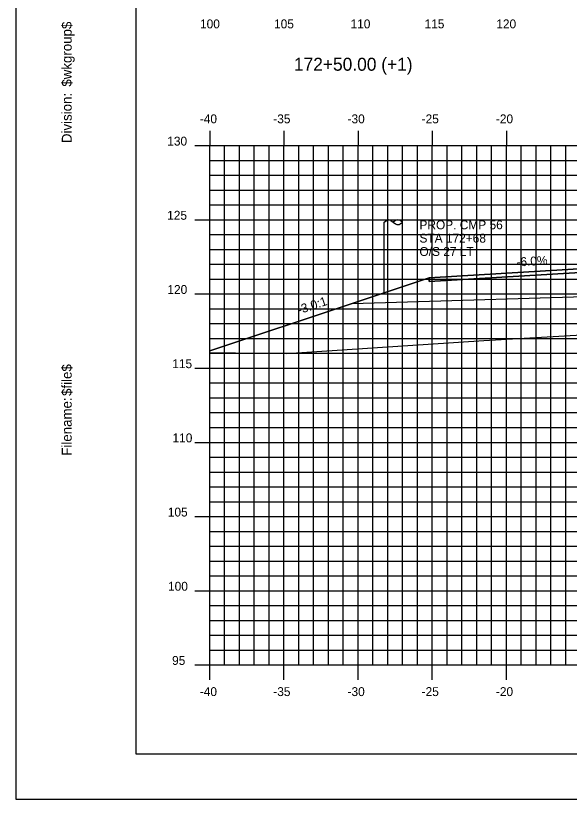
# Model space of a CAD drawing. Extents: x 850598 to 870284, y 366541 to 366651.
# Drawn here: x 856585.2 to 856622.6, y 366541.2 to 366594 of the extents above; entities that cross this region are included whole.
import ezdxf

# ---------------------------------------------------------------- set-up
doc = ezdxf.new("R2010")
doc.units = 0
for name, color, linetype in [('ANNOTATION', 7, 'Continuous'), ('BORDER', 7, 'Continuous'), ('D_Roadway_Centerline', 7, 'Continuous'), ('D_Roadway_Edge_Shoulder', 7, 'Continuous'), ('D_Roadway_SlopeLines', 7, 'Continuous'), ('D_Roadway_SubGrade', 7, 'Continuous'), ('D_Utilities_Pole_Joint', 7, 'Continuous'), ('H_V ANNOTATION', 7, 'Continuous'), ('MAJOR', 7, 'Continuous'), ('MINOR', 7, 'Continuous'), ('PLOT BOUNDARY', 7, 'Continuous'), ('S_Roadway_Centerline', 7, 'Continuous'), ('S_Utilities_Pole_Joint', 7, 'Continuous')]:
    doc.layers.add(name, color=color, linetype=linetype)

msp = doc.modelspace()

# ---------------------------------------------------------------- linework, layer by layer
at = {"layer": 'BORDER'}
for p, q in [((856593.324, 366649.225), (856593.324, 366544.225)), ((856593.324, 366544.225), (856753.324, 366544.225))]:
    msp.add_line(p, q, dxfattribs=at)
at = {"layer": 'D_Roadway_Centerline'}
msp.add_lwpolyline([(856598.324, 366571.386), (856607.935, 366574.589), (856613.124, 366576.319), (856627.324, 366577.171), (856638.324, 366577.501), (856649.324, 366577.171), (856653.324, 366576.931), (856655.324, 366576.811), (856661.324, 366574.811), (856719.255, 366563.221), (856738.324, 366559.406)], dxfattribs=at)
at = {"layer": 'D_Roadway_Edge_Shoulder'}
msp.add_lwpolyline([(856627.324, 366577.171), (856613.124, 366576.319), (856613.124, 366576.069), (856626.324, 366576.861), (856627.324, 366576.921)], close=True, dxfattribs=at)
at = {"layer": 'D_Roadway_SlopeLines'}
msp.add_lwpolyline([(856607.935, 366574.589), (856598.324, 366571.386)], dxfattribs=at)
at = {"layer": 'D_Roadway_SubGrade'}
msp.add_lwpolyline([(856627.324, 366576.671), (856626.324, 366576.611), (856626.324, 366576.861), (856613.124, 366576.069), (856613.124, 366576.319), (856607.935, 366574.589), (856627.324, 366575.171)], close=True, dxfattribs=at)
msp.add_lwpolyline([(856613.124, 366576.319), (856607.935, 366574.589), (856613.124, 366576.319)], dxfattribs=at)
at = {"layer": 'D_Utilities_Pole_Joint'}
for p, q in [((856610.074, 366580.061), (856610.23, 366580.171)), ((856610.074, 366575.303), (856610.074, 366580.061)), ((856610.542, 366580.171), (856610.698, 366580.061)), ((856610.854, 366580.171), (856610.698, 366580.061)), ((856610.698, 366580.061), (856610.854, 366579.95)), ((856611.324, 366580.061), (856611.167, 366580.171)), ((856611.167, 366579.95), (856611.324, 366580.061)), ((856611.324, 366575.303), (856611.324, 366580.061))]:
    msp.add_line(p, q, dxfattribs=at)
for centre, start, end in [((856610.386, 366579.95), 90, 125.2644), ((856610.386, 366579.95), 54.7356, 90), ((856611.011, 366579.95), 90, 125.2644), ((856611.011, 366580.171), 234.7356, 270), ((856611.011, 366579.95), 54.7356, 90), ((856611.011, 366580.171), 270, 305.2644)]:
    msp.add_arc(centre, 0.271, start, end, dxfattribs=at)
at = {"layer": 'MAJOR'}
for p, q in [((856598.324, 366586.227), (856598.324, 366585.225)), ((856598.324, 366586.227), (856598.324, 366585.225)), ((856603.324, 366586.227), (856603.324, 366585.225)), ((856603.324, 366586.227), (856603.324, 366585.225)), ((856608.324, 366586.227), (856608.324, 366585.225)), ((856608.324, 366586.227), (856608.324, 366585.225)), ((856613.324, 366586.227), (856613.324, 366585.225)), ((856613.324, 366586.227), (856613.324, 366585.225)), ((856618.324, 366586.227), (856618.324, 366585.225)), ((856618.324, 366586.227), (856618.324, 366585.225)), ((856597.322, 366585.225), (856598.324, 366585.225)), ((856597.322, 366585.225), (856598.324, 366585.225)), ((856598.324, 366585.225), (856738.324, 366585.225)), ((856598.324, 366550.225), (856598.324, 366585.225)), ((856598.324, 366550.225), (856598.324, 366585.225)), ((856598.324, 366585.225), (856738.324, 366585.225)), ((856598.324, 366585.225), (856738.324, 366585.225)), ((856598.324, 366550.225), (856598.324, 366585.225)), ((856598.324, 366550.225), (856598.324, 366585.225)), ((856598.324, 366585.225), (856738.324, 366585.225)), ((856603.324, 366550.225), (856603.324, 366585.225)), ((856603.324, 366550.225), (856603.324, 366585.225)), ((856608.324, 366550.225), (856608.324, 366585.225)), ((856608.324, 366550.225), (856608.324, 366585.225)), ((856613.324, 366550.225), (856613.324, 366585.225)), ((856613.324, 366550.225), (856613.324, 366585.225)), ((856618.324, 366550.225), (856618.324, 366585.225)), ((856618.324, 366550.225), (856618.324, 366585.225)), ((856597.322, 366580.225), (856598.324, 366580.225)), ((856597.322, 366580.225), (856598.324, 366580.225)), ((856598.324, 366580.225), (856738.324, 366580.225)), ((856598.324, 366580.225), (856738.324, 366580.225)), ((856597.322, 366575.225), (856598.324, 366575.225)), ((856597.322, 366575.225), (856598.324, 366575.225)), ((856598.324, 366575.225), (856738.324, 366575.225)), ((856598.324, 366575.225), (856738.324, 366575.225)), ((856597.322, 366570.225), (856598.324, 366570.225)), ((856597.322, 366570.225), (856598.324, 366570.225)), ((856598.324, 366570.225), (856738.324, 366570.225)), ((856598.324, 366570.225), (856738.324, 366570.225)), ((856597.322, 366565.225), (856598.324, 366565.225)), ((856597.322, 366565.225), (856598.324, 366565.225)), ((856598.324, 366565.225), (856738.324, 366565.225)), ((856598.324, 366565.225), (856738.324, 366565.225)), ((856597.322, 366560.225), (856598.324, 366560.225)), ((856597.322, 366560.225), (856598.324, 366560.225)), ((856598.324, 366560.225), (856738.324, 366560.225)), ((856598.324, 366560.225), (856738.324, 366560.225)), ((856597.322, 366555.225), (856598.324, 366555.225)), ((856597.322, 366555.225), (856598.324, 366555.225)), ((856598.324, 366555.225), (856738.324, 366555.225)), ((856598.324, 366555.225), (856738.324, 366555.225)), ((856597.322, 366550.225), (856598.324, 366550.225)), ((856597.322, 366550.225), (856598.324, 366550.225)), ((856598.324, 366550.225), (856738.324, 366550.225)), ((856598.324, 366550.225), (856738.324, 366550.225)), ((856598.324, 366549.223), (856598.324, 366550.225)), ((856598.324, 366550.225), (856738.324, 366550.225)), ((856598.324, 366550.225), (856738.324, 366550.225)), ((856598.324, 366549.223), (856598.324, 366550.225)), ((856603.324, 366549.223), (856603.324, 366550.225)), ((856603.324, 366549.223), (856603.324, 366550.225)), ((856608.324, 366549.223), (856608.324, 366550.225)), ((856608.324, 366549.223), (856608.324, 366550.225)), ((856613.324, 366549.223), (856613.324, 366550.225)), ((856613.324, 366549.223), (856613.324, 366550.225)), ((856618.324, 366549.223), (856618.324, 366550.225)), ((856618.324, 366549.223), (856618.324, 366550.225))]:
    msp.add_line(p, q, dxfattribs=at)
at = {"layer": 'MINOR'}
for p, q in [((856599.324, 366550.225), (856599.324, 366585.225)), ((856599.324, 366550.225), (856599.324, 366585.225)), ((856600.324, 366550.225), (856600.324, 366585.225)), ((856600.324, 366550.225), (856600.324, 366585.225)), ((856601.324, 366550.225), (856601.324, 366585.225)), ((856601.324, 366550.225), (856601.324, 366585.225)), ((856602.324, 366550.225), (856602.324, 366585.225)), ((856602.324, 366550.225), (856602.324, 366585.225)), ((856604.324, 366550.225), (856604.324, 366585.225)), ((856604.324, 366550.225), (856604.324, 366585.225)), ((856605.324, 366550.225), (856605.324, 366585.225)), ((856605.324, 366550.225), (856605.324, 366585.225)), ((856606.324, 366550.225), (856606.324, 366585.225)), ((856606.324, 366550.225), (856606.324, 366585.225)), ((856607.324, 366550.225), (856607.324, 366585.225)), ((856607.324, 366550.225), (856607.324, 366585.225)), ((856609.324, 366550.225), (856609.324, 366585.225)), ((856609.324, 366550.225), (856609.324, 366585.225)), ((856610.324, 366550.225), (856610.324, 366585.225)), ((856610.324, 366550.225), (856610.324, 366585.225)), ((856611.324, 366550.225), (856611.324, 366585.225)), ((856611.324, 366550.225), (856611.324, 366585.225)), ((856612.324, 366550.225), (856612.324, 366585.225)), ((856612.324, 366550.225), (856612.324, 366585.225)), ((856614.324, 366550.225), (856614.324, 366585.225)), ((856614.324, 366550.225), (856614.324, 366585.225)), ((856615.324, 366550.225), (856615.324, 366585.225)), ((856615.324, 366550.225), (856615.324, 366585.225)), ((856616.324, 366550.225), (856616.324, 366585.225)), ((856616.324, 366550.225), (856616.324, 366585.225)), ((856617.324, 366550.225), (856617.324, 366585.225)), ((856617.324, 366550.225), (856617.324, 366585.225)), ((856619.324, 366550.225), (856619.324, 366585.225)), ((856619.324, 366550.225), (856619.324, 366585.225)), ((856620.324, 366550.225), (856620.324, 366585.225)), ((856620.324, 366550.225), (856620.324, 366585.225)), ((856621.324, 366550.225), (856621.324, 366585.225)), ((856621.324, 366550.225), (856621.324, 366585.225)), ((856622.324, 366550.225), (856622.324, 366585.225)), ((856622.324, 366550.225), (856622.324, 366585.225)), ((856598.324, 366584.225), (856738.324, 366584.225)), ((856598.324, 366584.225), (856599.326, 366584.225)), ((856598.324, 366584.225), (856738.324, 366584.225)), ((856598.324, 366584.225), (856599.326, 366584.225)), ((856598.324, 366583.225), (856738.324, 366583.225)), ((856598.324, 366583.225), (856599.326, 366583.225)), ((856598.324, 366583.225), (856738.324, 366583.225)), ((856598.324, 366583.225), (856599.326, 366583.225)), ((856598.324, 366582.225), (856738.324, 366582.225)), ((856598.324, 366582.225), (856599.326, 366582.225)), ((856598.324, 366582.225), (856738.324, 366582.225)), ((856598.324, 366582.225), (856599.326, 366582.225)), ((856598.324, 366581.225), (856738.324, 366581.225)), ((856598.324, 366581.225), (856599.326, 366581.225)), ((856598.324, 366581.225), (856738.324, 366581.225)), ((856598.324, 366581.225), (856599.326, 366581.225)), ((856598.324, 366579.225), (856738.324, 366579.225)), ((856598.324, 366579.225), (856599.326, 366579.225)), ((856598.324, 366579.225), (856738.324, 366579.225)), ((856598.324, 366579.225), (856599.326, 366579.225)), ((856598.324, 366578.225), (856738.324, 366578.225)), ((856598.324, 366578.225), (856599.326, 366578.225)), ((856598.324, 366578.225), (856738.324, 366578.225)), ((856598.324, 366578.225), (856599.326, 366578.225)), ((856598.324, 366577.225), (856738.324, 366577.225)), ((856598.324, 366577.225), (856599.326, 366577.225)), ((856598.324, 366577.225), (856738.324, 366577.225)), ((856598.324, 366577.225), (856599.326, 366577.225)), ((856598.324, 366576.225), (856738.324, 366576.225)), ((856598.324, 366576.225), (856599.326, 366576.225)), ((856598.324, 366576.225), (856738.324, 366576.225)), ((856598.324, 366576.225), (856599.326, 366576.225)), ((856598.324, 366574.225), (856738.324, 366574.225)), ((856598.324, 366574.225), (856599.326, 366574.225)), ((856598.324, 366574.225), (856738.324, 366574.225)), ((856598.324, 366574.225), (856599.326, 366574.225)), ((856598.324, 366573.225), (856738.324, 366573.225)), ((856598.324, 366573.225), (856599.326, 366573.225)), ((856598.324, 366573.225), (856738.324, 366573.225)), ((856598.324, 366573.225), (856599.326, 366573.225)), ((856598.324, 366572.225), (856738.324, 366572.225)), ((856598.324, 366572.225), (856599.326, 366572.225)), ((856598.324, 366572.225), (856738.324, 366572.225)), ((856598.324, 366572.225), (856599.326, 366572.225)), ((856598.324, 366571.225), (856738.324, 366571.225)), ((856598.324, 366571.225), (856599.326, 366571.225)), ((856598.324, 366571.225), (856738.324, 366571.225)), ((856598.324, 366571.225), (856599.326, 366571.225)), ((856598.324, 366569.225), (856738.324, 366569.225)), ((856598.324, 366569.225), (856599.326, 366569.225)), ((856598.324, 366569.225), (856738.324, 366569.225)), ((856598.324, 366569.225), (856599.326, 366569.225)), ((856598.324, 366568.225), (856738.324, 366568.225)), ((856598.324, 366568.225), (856599.326, 366568.225)), ((856598.324, 366568.225), (856738.324, 366568.225)), ((856598.324, 366568.225), (856599.326, 366568.225)), ((856598.324, 366567.225), (856738.324, 366567.225)), ((856598.324, 366567.225), (856599.326, 366567.225)), ((856598.324, 366567.225), (856738.324, 366567.225)), ((856598.324, 366567.225), (856599.326, 366567.225)), ((856598.324, 366566.225), (856738.324, 366566.225)), ((856598.324, 366566.225), (856599.326, 366566.225)), ((856598.324, 366566.225), (856738.324, 366566.225)), ((856598.324, 366566.225), (856599.326, 366566.225)), ((856598.324, 366564.225), (856738.324, 366564.225)), ((856598.324, 366564.225), (856599.326, 366564.225)), ((856598.324, 366564.225), (856738.324, 366564.225)), ((856598.324, 366564.225), (856599.326, 366564.225)), ((856598.324, 366563.225), (856738.324, 366563.225)), ((856598.324, 366563.225), (856599.326, 366563.225)), ((856598.324, 366563.225), (856738.324, 366563.225)), ((856598.324, 366563.225), (856599.326, 366563.225)), ((856598.324, 366562.225), (856738.324, 366562.225)), ((856598.324, 366562.225), (856599.326, 366562.225)), ((856598.324, 366562.225), (856738.324, 366562.225)), ((856598.324, 366562.225), (856599.326, 366562.225)), ((856598.324, 366561.225), (856738.324, 366561.225)), ((856598.324, 366561.225), (856599.326, 366561.225)), ((856598.324, 366561.225), (856738.324, 366561.225)), ((856598.324, 366561.225), (856599.326, 366561.225)), ((856598.324, 366559.225), (856738.324, 366559.225)), ((856598.324, 366559.225), (856599.326, 366559.225)), ((856598.324, 366559.225), (856738.324, 366559.225)), ((856598.324, 366559.225), (856599.326, 366559.225)), ((856598.324, 366558.225), (856738.324, 366558.225)), ((856598.324, 366558.225), (856599.326, 366558.225)), ((856598.324, 366558.225), (856738.324, 366558.225)), ((856598.324, 366558.225), (856599.326, 366558.225)), ((856598.324, 366557.225), (856738.324, 366557.225)), ((856598.324, 366557.225), (856599.326, 366557.225)), ((856598.324, 366557.225), (856738.324, 366557.225)), ((856598.324, 366557.225), (856599.326, 366557.225)), ((856598.324, 366556.225), (856738.324, 366556.225)), ((856598.324, 366556.225), (856599.326, 366556.225)), ((856598.324, 366556.225), (856738.324, 366556.225)), ((856598.324, 366556.225), (856599.326, 366556.225)), ((856598.324, 366554.225), (856738.324, 366554.225)), ((856598.324, 366554.225), (856599.326, 366554.225)), ((856598.324, 366554.225), (856738.324, 366554.225)), ((856598.324, 366554.225), (856599.326, 366554.225)), ((856598.324, 366553.225), (856738.324, 366553.225)), ((856598.324, 366553.225), (856599.326, 366553.225)), ((856598.324, 366553.225), (856738.324, 366553.225)), ((856598.324, 366553.225), (856599.326, 366553.225)), ((856598.324, 366552.225), (856738.324, 366552.225)), ((856598.324, 366552.225), (856599.326, 366552.225)), ((856598.324, 366552.225), (856738.324, 366552.225)), ((856598.324, 366552.225), (856599.326, 366552.225)), ((856598.324, 366551.225), (856738.324, 366551.225)), ((856598.324, 366551.225), (856599.326, 366551.225)), ((856598.324, 366551.225), (856738.324, 366551.225)), ((856598.324, 366551.225), (856599.326, 366551.225))]:
    msp.add_line(p, q, dxfattribs=at)
at = {"layer": 'PLOT BOUNDARY'}
msp.add_lwpolyline([(856585.231, 366541.166), (856755.231, 366541.166), (856755.231, 366651.166), (856585.231, 366651.166)], close=True, dxfattribs=at)
at = {"layer": 'S_Roadway_Centerline'}
msp.add_lwpolyline([(856598.324, 366571.268), (856603.495, 366571.21), (856616.807, 366572.085), (856637.79, 366573.299), (856637.959, 366573.162), (856639.834, 366573.342), (856640.415, 366573.364), (856641.474, 366573.437), (856643.89, 366573.65), (856644.156, 366573.68), (856648.75, 366574.379), (856654.575, 366575.374), (856657.088, 366575.739), (856659.329, 366576.064), (856667.093, 366576.438)], dxfattribs=at)

# ---------------------------------------------------------------- texts
at = {"layer": 'ANNOTATION'}
for s, rotation, p in [('-6.0%', 3.4336, (856619.021, 366577.075)), ('-3.0:1', 18.4348, (856604.345, 366573.847))]:
    msp.add_text(s, height=0.6, rotation=rotation, dxfattribs=at).set_placement(p)
at = {"layer": 'BORDER'}
for s, p in [('$wkgroup$', (856589.009, 366589.195)), ('Division:', (856589.009, 366585.391)), ('$file$', (856589.009, 366568.351)), ('Filename:', (856589.009, 366564.324))]:
    msp.add_text(s, height=0.6696, rotation=90, dxfattribs=at).set_placement(p)
at = {"layer": 'H_V ANNOTATION'}
for s, height, p in [('100', 0.6, (856597.665, 366593.125)), ('105', 0.6, (856602.657, 366593.125)), ('110', 0.6, (856607.815, 366593.125)), ('115', 0.6, (856612.807, 366593.125)), ('120', 0.6, (856617.644, 366593.125)), ('172+50.00 (+1)', 0.87498, (856603.997, 366590.268)), ('-40', 0.6, (856597.649, 366586.725)), ('-35', 0.6, (856602.604, 366586.725)), ('-30', 0.6, (856607.612, 366586.725)), ('-25', 0.6, (856612.609, 366586.725)), ('-20', 0.6, (856617.617, 366586.725)), ('130', 0.6, (856595.454, 366585.225)), ('125', 0.6, (856595.448, 366580.225)), ('120', 0.6, (856595.464, 366575.225)), ('115', 0.6, (856595.791, 366570.225)), ('110', 0.6, (856595.807, 366565.225)), ('105', 0.6, (856595.491, 366560.225)), ('100', 0.6, (856595.507, 366555.225)), ('95', 0.6, (856595.78, 366550.225)), ('-40', 0.6, (856597.649, 366548.125)), ('-35', 0.6, (856602.604, 366548.125)), ('-30', 0.6, (856607.612, 366548.125)), ('-25', 0.6, (856612.609, 366548.125)), ('-20', 0.6, (856617.617, 366548.125))]:
    msp.add_text(s, height=height, dxfattribs=at).set_placement(p)
at = {"layer": 'S_Utilities_Pole_Joint'}
for s, p in [('PROP. CMP 56', (856612.463, 366579.584)), ('STA 172+68', (856612.463, 366578.684)), ('O/S 27 LT', (856612.463, 366577.784))]:
    msp.add_text(s, height=0.6, dxfattribs=at).set_placement(p)

doc.saveas('drawing.dxf')
